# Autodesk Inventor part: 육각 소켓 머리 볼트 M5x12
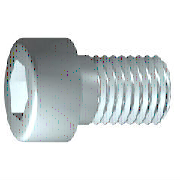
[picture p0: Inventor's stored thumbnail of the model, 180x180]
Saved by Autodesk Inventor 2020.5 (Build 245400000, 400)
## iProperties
Created: 2012-02
Part Number: 육각 소켓 머리 볼트 M5x12
Material: 강철, 연강
Description: 6각 소켓 머리 캡 나사
Document SubType Name: Modeling
Standard: ISO 4762
Designer: mdu-01
Standard Revision: Fourth edition 2004-03-01
Standards Organization: ISO
Language: ko-KR
Size Designation: M5 x 12
Categories: <MemberInstance><Categories><Category DisplayName="조임쇠" InternalName="e4da775c-781d-43d5-af7c-5136215cf5a6" Mnemonic="FSTN"><Category DisplayName="볼트" InternalN
Density: 7.75 g/cm^3
Appearance: 강철
IsCustomPart: 1
Author: mdu-01
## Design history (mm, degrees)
sketch "스케치1"
  geometry: L1 (-1.167, 0)-(12, 0); L2 (12, 0)-(12, 2.5); L3 (12, 2.5)-(2, 2.5); L4 (2, 2.5)-(1.509, 2.5); L5 (1.509, 2.5)-(0, 2.5); L6 (0, 2.5)-(0, 4.25); L7 (0, 4.25)-(-5, 4.25); L8 (-5, 4.25)-(-5, 2.309); L9 (-5, 2.309)-(-2.5, 2.309); L10 (-2.5, 2.309)-(-1.167, 0); L11 (-8.4, 0)-(15.4, 0) reference; L12 (0, -0.85)-(0, 5.1) reference; L13 (2, 2.5)-(0, 2.5)
  constraints: 22 end point, 6 parallel, 2 collinear, 2 perpendicular, 1 horizontal, 1 point on line
  dimensions: "d1" = 10 distance from line of L3.end L2 (= GEL); "d2" = 0.49086 distance of L4.end L3.end (computed from GAL); "d3" = 5 distance between parallel lines of L8 L6 (= KOH); "d4" = 2.5 distance of L8.end L9.end (= INTI); "d5" = 60 deg angle of L10 L1; "d6" = 5 diameter of L3 L1 (= GD); "d7" = 5 diameter of L5 L1 (= BDM); "d8" = 4.6188 diameter of L9 L1 (= 1.1547 x SW); "d9" = 8.5 diameter of L7 L1 (= KOD); "d26" = 12 distance between parallel lines of L12 L2 (= NLG)
revolve "본체" sketch "스케치1" stored, may be unused: angle "d10" = 90 deg
sketch "스케치2"
  geometry: L1 (0, -5.95)-(0, 5.95) reference; L2 (-5.95, 0)-(5.95, 0) reference; L3 (2.309, 0)-(1.155, -2); L4 (1.155, -2)-(-1.155, -2); L5 (-1.155, -2)-(-2.309, 0); L6 (-2.309, 0)-(-1.155, 2); L7 (-1.155, 2)-(1.155, 2); L8 (1.155, 2)-(2.309, 0); 2 further points
  constraints: 12 end point, 1 coincident, 1 horizontal alignment, 1 point on line, 12 other
extrude "슬롯" join sketch "스케치2" stored distance "d11" = 10; taper "d12" = 0 deg
workplane "Work Plane1"
fillet "Fillet2" dims "d30" = 0.1 (= R)
body "Solid1"
fillet "모깎기1" dims "d17" = 0.5 (= RR)
feature "스레드" dims "d13" = 10 (= GEL), "d14" = 0
chamfer "모따기1" distance "d15" = 0.49076 (= -0.5 x SPD + 0.5 x GD); stored, may be unused: second distance "d16" = 0.49076 (= GUL), angle "d27" = 45 deg
other parameters: "GD" = 5 [user parameter; used in 2 equation terms], "NLG" = 12 [user parameter; used in 1 equation term], "GEL" = 10 [user parameter; used in 2 equation terms], "KOD" = 8.5 [user parameter; used in 1 equation term], "KOH" = 5 [user parameter; used in 1 equation term], "INTI" = 2.5 [user parameter; used in 1 equation term], "GAL" = 0.49076 (= 0.61345 x PTC) [user parameter; used in 1 equation term], "GUL" = 0.49076 (= 0.61345 x PTC) [user parameter; used in 1 equation term], "BDM" = 5 (= NND) [user parameter; used in 1 equation term], "SW" = 4 [user parameter; used in 2 equation terms], "RR" = 0.5 [user parameter; used in 1 equation term], "SPD" = 4.01848 (= NND - 1.2269 x PTC) [user parameter; used in 1 equation term], "d19" = 0, "d28" = 0, "d29" = 0, "R" = 0.1 [user parameter; used in 1 equation term], "TOA" = 30 deg [user parameter], "GD1" = 4.01848 (= THREADDIA - 1.2269 x PTC) [user parameter], "THREADDIA" = 5 [user parameter; used in 1 equation term], "FAWI" = 45 deg [user parameter], "TPU" = 12.5 (computed from PTC) [user parameter], "PTC" = 0.8 [user parameter; used in 5 equation terms], "NND" = 5 [user parameter; used in 2 equation terms], "E0" = 4.62 (= 1.155 x SW) [user parameter]
